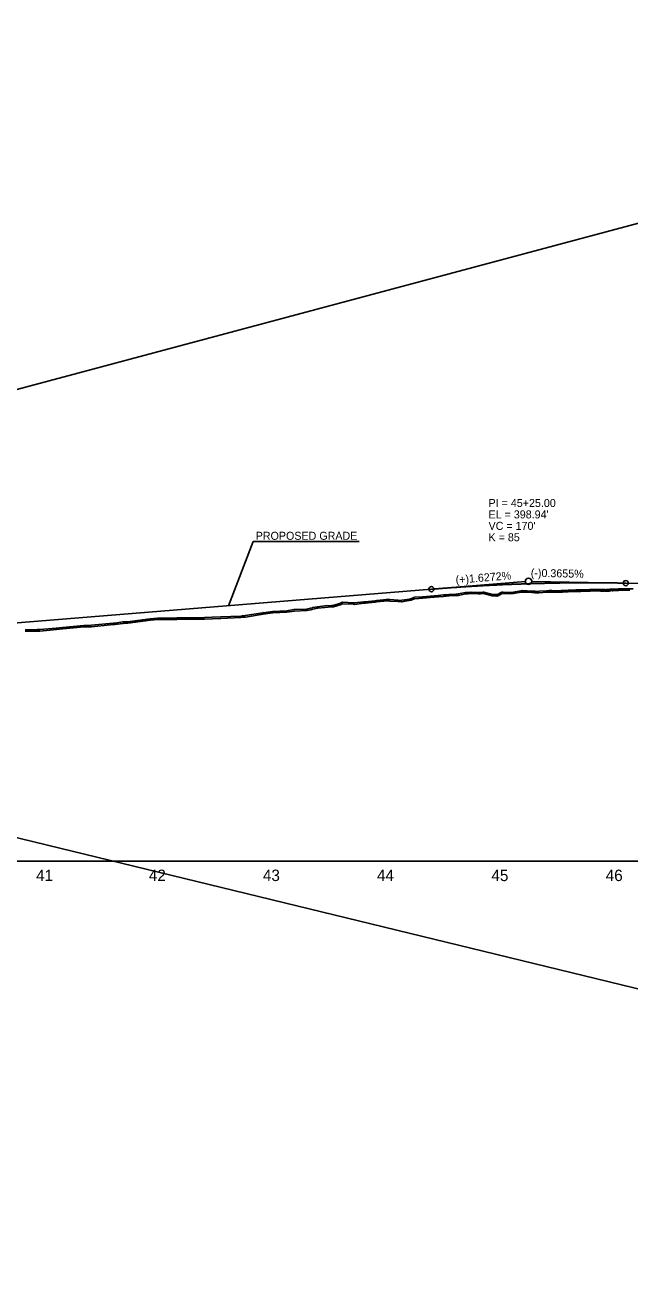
# Model space of a CAD drawing. Extents: x 1625686 to 1640492, y 1161393 to 1175642.
# Drawn here: x 1638996 to 1639525, y 1174544 to 1175642 of the extents above; entities that cross this region are included whole.
import ezdxf

# ---------------------------------------------------------------- set-up
doc = ezdxf.new("R2010")
doc.units = 0
for name, color, linetype in [('Exist Profile Cell', 7, 'Continuous'), ('Exist Vertical Profile Horizontal Axis Label Major', 7, 'Continuous'), ('Prop Vertical Profile Curve Label', 7, 'Continuous'), ('Prop Vertical Profile Grade', 7, 'Continuous'), ('Prop Vertical Profile Grade Label', 7, 'Continuous'), ('Prop VPI Label', 7, 'Continuous'), ('Scratch_Level_1', 7, 'Continuous'), ('Scratch_Level_3', 7, 'Continuous')]:
    doc.layers.add(name, color=color, linetype=linetype)

msp = doc.modelspace()

# ---------------------------------------------------------------- linework, layer by layer
at = {"layer": 'Exist Profile Cell'}
msp.add_line((1635911.8, 1174910.8), (1640378.1, 1174910.8), dxfattribs=at)
at = {"layer": 'Prop Vertical Profile Curve Label'}
for centre in [(1639351.8, 1175148.6), (1639521.8, 1175153.9)]:
    msp.add_circle(centre, 2.25, dxfattribs=at)
at = {"layer": 'Prop Vertical Profile Grade'}
for p, q in [((1639521.8, 1175153.9), (1639936.8, 1175146.4)), ((1638766.8, 1175101), (1639351.8, 1175148.6))]:
    msp.add_line(p, q, dxfattribs=at)
msp.add_spline([(1639351.8, 1175148.6), (1639355.2, 1175148.8), (1639358.6, 1175149.1), (1639362, 1175149.4), (1639365.4, 1175149.6), (1639368.8, 1175149.9), (1639372.2, 1175150.1), (1639375.6, 1175150.3), (1639379, 1175150.6), (1639382.4, 1175150.8), (1639385.8, 1175151), (1639389.2, 1175151.2), (1639392.6, 1175151.4), (1639396, 1175151.6), (1639399.4, 1175151.8), (1639402.8, 1175152), (1639406.2, 1175152.1), (1639409.6, 1175152.3), (1639413, 1175152.5), (1639416.4, 1175152.6), (1639419.8, 1175152.7), (1639423.2, 1175152.9), (1639426.6, 1175153), (1639430, 1175153.1), (1639433.4, 1175153.3), (1639436.8, 1175153.4), (1639440.2, 1175153.5), (1639443.6, 1175153.6), (1639447, 1175153.7), (1639450.4, 1175153.7), (1639453.8, 1175153.8), (1639457.2, 1175153.9), (1639460.6, 1175154), (1639464, 1175154), (1639467.4, 1175154.1), (1639470.8, 1175154.1), (1639474.2, 1175154.1), (1639477.6, 1175154.2), (1639481, 1175154.2), (1639484.4, 1175154.2), (1639487.8, 1175154.2), (1639491.2, 1175154.2), (1639494.6, 1175154.2), (1639498, 1175154.2), (1639501.4, 1175154.2), (1639504.8, 1175154.2), (1639508.2, 1175154.1), (1639511.6, 1175154.1), (1639515, 1175154), (1639518.4, 1175154), (1639521.8, 1175153.9)], degree=3, dxfattribs=at)
at = {"layer": 'Prop VPI Label'}
for p, q in [((1639196, 1175190.4), (1639174.3, 1175134.1)), ((1639288.6, 1175190.4), (1639196, 1175190.4)), ((1639351.8, 1175148.6), (1639434, 1175155.3)), ((1639521.8, 1175153.9), (1639439.5, 1175155.4))]:
    msp.add_line(p, q, dxfattribs=at)
msp.add_circle((1639436.8, 1175155.5), 2.75, dxfattribs=at)
at = {"layer": 'Scratch_Level_1'}
for p, q in [((1639303.9, 1175138.6), (1639309.9, 1175139.4)), ((1639310, 1175139.4), (1639312.2, 1175139.6)), ((1639310.1, 1175138.1), (1639312.3, 1175138.3)), ((1639312.3, 1175139.6), (1639312.6, 1175139.6)), ((1639312.4, 1175138.3), (1639312.7, 1175138.4)), ((1639381.8, 1175145.7), (1639384, 1175145.8)), ((1639381.9, 1175144.4), (1639384, 1175144.6)), ((1639384, 1175145.8), (1639386.2, 1175146)), ((1639384.1, 1175144.6), (1639386.3, 1175144.7)), ((1639411, 1175144.9), (1639413.3, 1175145.9)), ((1639411.6, 1175143.7), (1639413.8, 1175144.8)), ((1639431.9, 1175147.3), (1639435.6, 1175147.1)), ((1639431.9, 1175146.1), (1639435.5, 1175145.9)), ((1639435.5, 1175145.9), (1639439.8, 1175145.7)), ((1639435.6, 1175147.1), (1639439.9, 1175146.9)), ((1639439.8, 1175145.7), (1639442.4, 1175145.5)), ((1639439.9, 1175146.9), (1639442.4, 1175146.8)), ((1639457, 1175146.1), (1639461.2, 1175145.9)), ((1639457.1, 1175147.4), (1639461.3, 1175147.2)), ((1639465.3, 1175147.3), (1639466.5, 1175147.4)), ((1639465.4, 1175146.1), (1639466.6, 1175146.1)), ((1639466.6, 1175147.4), (1639469.6, 1175147.5)), ((1639466.6, 1175146.1), (1639469.7, 1175146.3)), ((1639473.4, 1175147.7), (1639473.9, 1175147.7)), ((1639473.5, 1175146.5), (1639474, 1175146.5)), ((1639473.9, 1175147.7), (1639478.3, 1175147.9)), ((1639474, 1175146.5), (1639478.3, 1175146.7)), ((1639482.5, 1175148), (1639485, 1175148.1)), ((1639482.6, 1175146.7), (1639485, 1175146.8)), ((1639485, 1175148.1), (1639486.8, 1175148.1)), ((1639485, 1175146.8), (1639486.9, 1175146.9)), ((1639491.5, 1175148.3), (1639495.5, 1175148.3)), ((1639491.5, 1175147.1), (1639495.5, 1175147.1)), ((1639495.5, 1175148.3), (1639496.9, 1175148.3)), ((1639495.5, 1175147.1), (1639496.9, 1175147.1)), ((1639496.9, 1175148.3), (1639499.8, 1175148.3)), ((1639496.9, 1175147.1), (1639499.8, 1175147)), ((1639504.9, 1175148.2), (1639506.1, 1175148.3)), ((1639505, 1175147), (1639506.2, 1175147)), ((1639508.7, 1175148.5), (1639509.9, 1175148.5)), ((1639510.3, 1175148.5), (1639512.8, 1175148.7)), ((1639510.4, 1175147.3), (1639512.8, 1175147.4)), ((1639512.8, 1175148.7), (1639514.2, 1175148.7)), ((1639512.9, 1175147.4), (1639514.2, 1175147.5)), ((1639516.8, 1175148.8), (1639517.2, 1175148.8)), ((1639516.9, 1175147.6), (1639517.3, 1175147.6)), ((1639517.2, 1175148.8), (1639518.1, 1175148.8)), ((1639517.3, 1175147.6), (1639518.1, 1175147.6)), ((1639524, 1175148.9), (1639525.5, 1175148.9)), ((1639524, 1175147.6), (1639525.5, 1175147.6)), ((1639204.5, 1175128), (1639212.8, 1175129)), ((1639204.7, 1175126.8), (1639212.9, 1175127.8)), ((1639247.9, 1175132.5), (1639252.1, 1175133.2)), ((1639248.1, 1175131.2), (1639252.3, 1175131.9)), ((1639252.2, 1175133.2), (1639258.6, 1175133.9)), ((1639252.4, 1175131.9), (1639258.7, 1175132.6)), ((1639258.7, 1175133.9), (1639264.3, 1175134.3)), ((1639258.7, 1175132.6), (1639264.4, 1175133.1)), ((1639274.3, 1175137.1), (1639283.4, 1175136.8)), ((1639274.3, 1175135.8), (1639283.4, 1175135.6)), ((1639304.1, 1175137.4), (1639310, 1175138.1)), ((1639105.9, 1175122.8), (1639109.1, 1175123.1)), ((1639106.1, 1175121.6), (1639109.2, 1175121.9)), ((1639109.3, 1175123.1), (1639112.2, 1175123.2)), ((1639109.3, 1175121.9), (1639112.2, 1175122))]:
    msp.add_line(p, q, dxfattribs=at)
for points in [[(1639293, 1175137.5), (1639294.1, 1175137.5), (1639302.3, 1175138.3), (1639303.8, 1175138.6)], [(1639312.9, 1175139.6), (1639315.4, 1175139.5), (1639322.7, 1175139.1)], [(1639312.9, 1175138.4), (1639315.3, 1175138.2), (1639322.6, 1175137.9)], [(1639322.8, 1175139.1), (1639325.7, 1175138.8), (1639326, 1175138.9), (1639328.4, 1175139.4)], [(1639328.6, 1175139.4), (1639332.3, 1175140), (1639333.9, 1175140.2), (1639336.3, 1175141.3)], [(1639328.8, 1175138.2), (1639332.5, 1175138.7), (1639334.2, 1175139), (1639336.8, 1175140.1)], [(1639337.1, 1175141.5), (1639344.1, 1175142), (1639350.6, 1175142.5), (1639354.1, 1175142.8), (1639357.8, 1175143.2), (1639362.3, 1175143.6)], [(1639337.2, 1175140.2), (1639344.2, 1175140.7), (1639350.7, 1175141.2), (1639354.2, 1175141.6), (1639358, 1175141.9), (1639362.5, 1175142.3)], [(1639362.4, 1175143.6), (1639364.7, 1175143.8), (1639367.1, 1175143.9)], [(1639362.5, 1175142.3), (1639364.8, 1175142.5), (1639367.2, 1175142.7)], [(1639367.1, 1175143.9), (1639373.2, 1175144.3), (1639375.3, 1175144.4), (1639381.5, 1175145.6)], [(1639367.2, 1175142.7), (1639373.3, 1175143), (1639375.5, 1175143.1), (1639381.7, 1175144.4)], [(1639386.4, 1175144.7), (1639392.7, 1175144.4), (1639394.8, 1175144.6), (1639397, 1175144.7)], [(1639386.5, 1175146), (1639392.7, 1175145.7), (1639394.7, 1175145.8), (1639396.9, 1175146)], [(1639397.4, 1175144.7), (1639405, 1175142.8), (1639409.1, 1175142.6), (1639410, 1175142.7), (1639410.8, 1175143.1), (1639411.2, 1175143.5)], [(1639397.7, 1175145.9), (1639405.2, 1175144), (1639409.1, 1175143.9), (1639409.7, 1175143.9), (1639410.1, 1175144.1), (1639410.4, 1175144.4)], [(1639414.4, 1175144.9), (1639420.3, 1175144.5), (1639423.5, 1175144.7), (1639430.3, 1175145.9)], [(1639414.5, 1175146.1), (1639420.3, 1175145.8), (1639423.3, 1175145.9), (1639430.1, 1175147.2)], [(1639430.5, 1175147.2), (1639431, 1175147.2), (1639431.6, 1175147.3)], [(1639430.5, 1175146), (1639431.1, 1175146), (1639431.7, 1175146)], [(1639442.4, 1175145.5), (1639444.1, 1175145.4), (1639446.2, 1175145.5), (1639452.8, 1175146)], [(1639442.5, 1175146.8), (1639444.1, 1175146.7), (1639446.1, 1175146.8), (1639452.7, 1175147.2)], [(1639452.7, 1175147.2), (1639454.7, 1175147.3), (1639456.8, 1175147.4)], [(1639452.8, 1175146), (1639454.7, 1175146), (1639456.9, 1175146.1)], [(1639461.2, 1175145.9), (1639462.2, 1175145.9), (1639465.4, 1175146.1)], [(1639461.3, 1175147.2), (1639462.2, 1175147.2), (1639465.3, 1175147.3)], [(1639469.6, 1175147.5), (1639471.4, 1175147.6), (1639473.4, 1175147.7)], [(1639469.7, 1175146.3), (1639471.4, 1175146.4), (1639473.5, 1175146.5)], [(1639478.4, 1175147.9), (1639480.2, 1175147.9), (1639482.5, 1175148)], [(1639478.4, 1175146.7), (1639480.2, 1175146.6), (1639482.6, 1175146.7)], [(1639486.8, 1175148.1), (1639490.2, 1175148.2), (1639491.2, 1175148.3)], [(1639486.9, 1175146.9), (1639490.3, 1175147), (1639491.3, 1175147.1)], [(1639499.8, 1175148.3), (1639502.2, 1175148.3), (1639502.9, 1175148.3)], [(1639499.8, 1175147), (1639502.2, 1175147), (1639502.9, 1175147)], [(1639503.4, 1175146.9), (1639503.6, 1175146.9), (1639504.1, 1175146.9), (1639504.9, 1175147)], [(1639503.8, 1175148.1), (1639504, 1175148.1), (1639504.8, 1175148.2)], [(1639506.2, 1175147), (1639507.3, 1175147), (1639508.2, 1175147.3)], [(1639506.3, 1175148.3), (1639507.1, 1175148.3), (1639507.8, 1175148.5)], [(1639508.6, 1175147.3), (1639510, 1175147.2), (1639510.1, 1175147.2)], [(1639514.3, 1175148.7), (1639515.4, 1175148.8), (1639516.8, 1175148.8)], [(1639514.3, 1175147.5), (1639515.4, 1175147.5), (1639516.9, 1175147.6)], [(1639518.1, 1175148.8), (1639519.2, 1175148.8), (1639521.1, 1175148.9)], [(1639518.1, 1175147.6), (1639519.2, 1175147.6), (1639521.2, 1175147.6)], [(1639521.2, 1175148.9), (1639523.4, 1175148.9), (1639524, 1175148.9)], [(1639521.2, 1175147.6), (1639523.4, 1175147.6), (1639524, 1175147.6)], [(1639525.5, 1175148.9), (1639525.9, 1175148.9), (1639527, 1175148.9), (1639528.4, 1175148.9)], [(1639186.8, 1175125.4), (1639188.9, 1175125.5), (1639204.4, 1175128)], [(1639212.9, 1175129), (1639225.2, 1175129.8), (1639231.6, 1175130.7)], [(1639213, 1175127.8), (1639225.3, 1175128.5), (1639231.8, 1175129.4)], [(1639231.8, 1175130.7), (1639242.6, 1175131.2), (1639246, 1175131.9), (1639247.6, 1175132.4)], [(1639231.9, 1175129.4), (1639242.7, 1175130), (1639246.3, 1175130.6), (1639248, 1175131.2)], [(1639264.3, 1175134.3), (1639265.9, 1175134.4), (1639272.3, 1175136.5), (1639273.2, 1175136.9)], [(1639264.4, 1175133.1), (1639266.1, 1175133.2), (1639272.8, 1175135.3), (1639273.7, 1175135.7)], [(1639283.7, 1175135.5), (1639284.4, 1175135.3), (1639292.8, 1175136.3)], [(1639284.1, 1175136.7), (1639284.5, 1175136.6), (1639292.7, 1175137.5)], [(1639293, 1175136.3), (1639294.2, 1175136.3), (1639302.4, 1175137.1), (1639304, 1175137.4)], [(1639322.7, 1175137.9), (1639325.7, 1175137.6), (1639326.2, 1175137.6), (1639328.7, 1175138.2)], [(1639029.2, 1175115), (1639047.8, 1175116.9), (1639048.5, 1175116.9)], [(1639048.7, 1175116.9), (1639054.3, 1175117), (1639073.5, 1175119)], [(1639048.7, 1175115.7), (1639054.3, 1175115.8), (1639073.6, 1175117.7)], [(1639073.7, 1175119), (1639074.8, 1175119), (1639081.9, 1175119.9)], [(1639073.7, 1175117.7), (1639074.9, 1175117.7), (1639082, 1175118.6)], [(1639082.1, 1175119.9), (1639086, 1175120.1), (1639105.8, 1175122.8)], [(1639082.1, 1175118.6), (1639086.1, 1175118.8), (1639106, 1175121.5)], [(1639112.2, 1175123.2), (1639126.1, 1175123.2), (1639129.1, 1175123.4)], [(1639112.2, 1175122), (1639126.1, 1175122), (1639129.1, 1175122.1)], [(1639129.2, 1175123.4), (1639150.9, 1175123.6), (1639153.3, 1175123.8)], [(1639129.2, 1175122.1), (1639150.9, 1175122.4), (1639153.3, 1175122.5)], [(1639153.3, 1175123.8), (1639160.1, 1175124.1), (1639167.5, 1175124.4)], [(1639153.3, 1175122.5), (1639160.2, 1175122.8), (1639167.5, 1175123.1)], [(1639167.5, 1175124.4), (1639185, 1175125.1), (1639186.4, 1175125.4)], [(1639167.5, 1175123.1), (1639185.1, 1175123.9), (1639186.6, 1175124.1)], [(1639186.8, 1175124.1), (1639189.1, 1175124.2), (1639204.6, 1175126.8)], [(1638996.3, 1175113.1), (1639007, 1175113.2), (1639009.1, 1175113.3), (1639023.6, 1175114.5), (1639029.2, 1175115)], [(1638996.3, 1175111.9), (1639007, 1175111.9), (1639009.2, 1175112), (1639023.8, 1175113.2), (1639029.4, 1175113.8)], [(1639029.4, 1175113.8), (1639047.9, 1175115.6), (1639048.6, 1175115.7)]]:
    msp.add_lwpolyline(points, dxfattribs=at)
for centre, radius, start, end in [((1639304.3, 1175136.1), 2.5, 97.3926, 100.858), ((1639310.2, 1175136.9), 2.5, 94.6193, 97.3926), ((1639312.4, 1175137.1), 2.5, 93.9476, 94.6193), ((1639312.4, 1175137.1), 1.25, 93.9476, 94.6193), ((1639312.8, 1175137.1), 2.5, 87.1466, 93.9476), ((1639312.8, 1175137.1), 1.25, 87.1466, 93.9476), ((1639322.6, 1175136.7), 2.5, 84.1047, 87.3612), ((1639328.9, 1175136.9), 2.5, 98.3239, 102.1934), ((1639337.3, 1175139), 2.5, 94.2508, 112.9541), ((1639337.3, 1175139), 1.25, 94.2508, 112.9541), ((1639362.6, 1175141.1), 2.5, 94.2169, 95.4818), ((1639362.6, 1175141.1), 1.25, 94.2169, 95.4818), ((1639367.3, 1175141.4), 2.5, 92.9168, 94.3822), ((1639367.3, 1175141.4), 1.25, 92.9168, 94.3822), ((1639382, 1175143.2), 2.5, 94.1965, 101.4805), ((1639382, 1175143.2), 1.25, 94.1965, 101.4805), ((1639384.1, 1175143.3), 2.5, 93.7655, 94.1965), ((1639384.1, 1175143.3), 1.25, 93.7655, 94.1965), ((1639386.4, 1175143.5), 2.5, 87.3911, 93.7655), ((1639386.4, 1175143.5), 1.25, 87.3911, 93.7655), ((1639397.1, 1175143.5), 2.5, 76.0153, 93.9476), ((1639397.1, 1175143.5), 1.25, 76.0153, 93.9476), ((1639412.1, 1175142.6), 2.5, 114.7526, 133.7236), ((1639412.1, 1175142.6), 1.25, 114.7526, 133.7236), ((1639414.4, 1175143.6), 2.5, 86.6248, 114.7526), ((1639414.4, 1175143.6), 1.25, 86.6248, 114.7526), ((1639430.6, 1175144.7), 2.5, 92.7649, 100.4912), ((1639430.6, 1175144.7), 1.25, 92.7649, 100.4912), ((1639431.8, 1175144.8), 2.5, 87.2388, 94.9283), ((1639431.8, 1175144.8), 1.25, 87.2388, 94.9283), ((1639435.4, 1175144.6), 1.25, 87.2354, 87.2388), ((1639435.4, 1175144.6), 2.5, 87.2354, 87.2388), ((1639439.7, 1175144.4), 1.25, 87.2321, 87.2354), ((1639439.7, 1175144.4), 2.5, 87.2321, 87.2354), ((1639442.3, 1175144.3), 2.5, 86.689, 87.2321), ((1639442.3, 1175144.3), 1.25, 86.689, 87.2321), ((1639452.8, 1175144.7), 2.5, 92.2481, 93.8382), ((1639452.8, 1175144.7), 1.25, 92.2481, 93.8382), ((1639457, 1175144.9), 2.5, 87.421, 92.5346), ((1639457, 1175144.9), 1.25, 87.421, 92.5346), ((1639461.2, 1175144.7), 1.25, 87.4111, 87.421), ((1639461.2, 1175144.7), 2.5, 87.4111, 87.421), ((1639465.5, 1175144.8), 2.5, 93.1155, 93.128), ((1639465.5, 1175144.8), 1.25, 93.1155, 93.128), ((1639466.7, 1175144.9), 2.5, 92.4381, 93.1155), ((1639466.7, 1175144.9), 1.25, 92.4381, 93.1155), ((1639469.7, 1175145), 2.5, 92.4254, 92.4381), ((1639469.7, 1175145), 1.25, 92.4254, 92.4381), ((1639473.5, 1175145.2), 2.5, 92.5421, 93.023), ((1639473.5, 1175145.2), 1.25, 92.5421, 93.023), ((1639474, 1175145.2), 2.5, 92.53, 92.5421), ((1639474, 1175145.2), 1.25, 92.53, 92.5421), ((1639478.4, 1175145.4), 2.5, 89.1847, 92.53), ((1639478.4, 1175145.4), 1.25, 89.1847, 92.53), ((1639482.6, 1175145.5), 2.5, 91.9474, 91.9636), ((1639482.6, 1175145.5), 1.25, 91.9474, 91.9636), ((1639485.1, 1175145.6), 2.5, 91.5664, 91.9474), ((1639485.1, 1175145.6), 1.25, 91.5664, 91.9474), ((1639486.9, 1175145.6), 2.5, 91.5501, 91.5664), ((1639486.9, 1175145.6), 1.25, 91.5501, 91.5664), ((1639491.5, 1175145.8), 2.5, 89.9405, 96.2914), ((1639491.5, 1175145.8), 1.25, 89.9405, 96.2914), ((1639495.5, 1175145.8), 2.5, 89.9331, 89.9405), ((1639495.5, 1175145.8), 1.25, 89.9331, 89.9405), ((1639496.9, 1175145.8), 2.5, 89.4016, 89.9331), ((1639496.9, 1175145.8), 1.25, 89.4016, 89.9331), ((1639499.8, 1175145.8), 2.5, 89.394, 89.4016), ((1639499.8, 1175145.8), 1.25, 89.394, 89.4016), ((1639503, 1175145.8), 2.5, 69.4483, 91.8684), ((1639503, 1175145.8), 1.25, 66.9741, 91.8684), ((1639505, 1175145.7), 2.5, 91.9853, 95.7529), ((1639505, 1175145.7), 1.25, 91.9853, 95.7529), ((1639506.2, 1175145.8), 2.5, 89.3174, 91.9853), ((1639506.2, 1175145.8), 1.25, 89.3174, 91.9853), ((1639508.5, 1175146), 2.5, 85.9806, 105.5959), ((1639508.5, 1175146), 1.25, 85.9806, 105.5959), ((1639510.5, 1175146), 2.5, 93.1907, 104.5413), ((1639510.5, 1175146), 1.25, 93.1907, 107.416), ((1639512.9, 1175146.2), 2.5, 92.7647, 93.1907), ((1639512.9, 1175146.2), 1.25, 92.7647, 93.1907), ((1639514.3, 1175146.2), 2.5, 91.1256, 92.7647), ((1639514.3, 1175146.2), 1.25, 91.1256, 92.7647), ((1639516.9, 1175146.3), 2.5, 91.4585, 91.4846), ((1639516.9, 1175146.3), 1.25, 91.4585, 91.4846), ((1639517.3, 1175146.3), 2.5, 91.3484, 91.4585), ((1639517.3, 1175146.3), 1.25, 91.3484, 91.4585), ((1639518.1, 1175146.3), 2.5, 90.9329, 91.3484), ((1639518.1, 1175146.3), 1.25, 90.9329, 91.3484), ((1639521.2, 1175146.4), 2.5, 89.9004, 91.3294), ((1639521.2, 1175146.4), 1.25, 89.9004, 91.3294), ((1639524, 1175146.4), 2.5, 90.1898, 90.464), ((1639524, 1175146.4), 1.25, 90.1898, 90.464), ((1639525.5, 1175146.4), 2.5, 90.1614, 90.1898), ((1639204.8, 1175125.6), 2.5, 96.7976, 99.3617), ((1639213, 1175126.5), 2.5, 93.4365, 96.7976), ((1639213, 1175126.5), 1.25, 93.4365, 96.7976), ((1639232, 1175128.2), 2.5, 92.8256, 97.7721), ((1639232, 1175128.2), 1.25, 92.8256, 97.7721), ((1639248.3, 1175130), 2.5, 99.421, 107.9697), ((1639248.3, 1175130), 1.25, 99.421, 107.9697), ((1639252.5, 1175130.7), 2.5, 96.3811, 99.421), ((1639252.5, 1175130.7), 1.25, 96.3811, 99.421), ((1639258.8, 1175131.4), 2.5, 94.1736, 96.3811), ((1639258.8, 1175131.4), 1.25, 94.1736, 96.3811), ((1639264.5, 1175131.8), 2.5, 93.5481, 94.1736), ((1639264.5, 1175131.8), 1.25, 93.5481, 94.1736), ((1639274.2, 1175134.6), 2.5, 88.3729, 113.7703), ((1639274.2, 1175134.6), 1.25, 88.3729, 113.7703), ((1639283.3, 1175134.3), 2.5, 71.3999, 88.3729), ((1639283.3, 1175134.3), 1.25, 71.3999, 88.3729), ((1639293, 1175135), 2.5, 89.8778, 96.536), ((1639293, 1175135), 1.25, 89.8778, 96.536), ((1639304.3, 1175136.1), 1.25, 97.3926, 100.858), ((1639310.2, 1175136.9), 1.25, 94.6193, 97.3926), ((1639322.6, 1175136.7), 1.25, 84.1047, 87.3612), ((1639328.9, 1175136.9), 1.25, 98.3239, 102.1934), ((1639048.7, 1175114.4), 2.5, 90.944, 95.8571), ((1639073.8, 1175116.5), 2.5, 90.8298, 95.7145), ((1639073.8, 1175116.5), 1.25, 90.8298, 95.7145), ((1639082.2, 1175117.4), 2.5, 92.7936, 96.9762), ((1639082.2, 1175117.4), 1.25, 92.7936, 96.9762), ((1639106.2, 1175120.3), 2.5, 96.1185, 97.8277), ((1639106.2, 1175120.3), 1.25, 96.1185, 97.8277), ((1639109.3, 1175120.6), 2.5, 91.0814, 96.1185), ((1639109.3, 1175120.6), 1.25, 91.0814, 96.1185), ((1639112.2, 1175120.7), 2.5, 90.1366, 91.0814), ((1639112.2, 1175120.7), 1.25, 90.1366, 91.0814), ((1639129.2, 1175120.9), 2.5, 90.6378, 92.9195), ((1639129.2, 1175120.9), 1.25, 90.6378, 92.9195), ((1639153.4, 1175121.3), 2.5, 92.4366, 93.0502), ((1639153.4, 1175121.3), 1.25, 92.4366, 93.0502), ((1639167.6, 1175121.9), 2.5, 92.432, 92.4462), ((1639167.6, 1175121.9), 1.25, 92.432, 92.4462), ((1639186.9, 1175122.9), 2.5, 92.3737, 99.7421), ((1639186.9, 1175122.9), 1.25, 92.3737, 99.7421), ((1639204.8, 1175125.6), 1.25, 96.7976, 99.3617), ((1639029.5, 1175112.5), 2.5, 95.642, 95.8083), ((1639029.5, 1175112.5), 1.25, 95.642, 95.8083), ((1639048.7, 1175114.4), 1.25, 90.944, 95.8571)]:
    msp.add_arc(centre, radius, start, end, dxfattribs=at)
at = {"layer": 'Scratch_Level_3'}
for p, q in [((1636069.4, 1175642), (1640127.7, 1174654.2)), ((1636080.3, 1174544.5), (1640138.7, 1175631))]:
    msp.add_line(p, q, dxfattribs=at)
msp.add_lwpolyline([(1635911.8, 1174910.8), (1640049.2, 1174910.8), (1640049.2, 1175362.5)], dxfattribs=at)

# ---------------------------------------------------------------- texts
at = {"layer": 'Exist Vertical Profile Horizontal Axis Label Major'}
for s, p in [('41', (1639006, 1174893.3)), ('42', (1639104.6, 1174893.3)), ('43', (1639204.4, 1174893.3)), ('44', (1639304.2, 1174893.3)), ('45', (1639404.3, 1174893.3)), ('46', (1639504.3, 1174893.3))]:
    msp.add_text(s, height=10, dxfattribs=at).set_placement(p)
at = {"layer": 'Prop Vertical Profile Curve Label'}
for s, p in [("VC = 170'", (1639401.8, 1175200.5)), ('K = 85', (1639401.8, 1175190.5))]:
    msp.add_text(s, height=7, dxfattribs=at).set_placement(p)
at = {"layer": 'Prop Vertical Profile Grade Label'}
for s, rotation, p in [('(+)1.6272%', 4.6514, (1639373.3, 1175153.3)), ('(-)0.3655%', 358.9532, (1639438.7, 1175159.4))]:
    msp.add_text(s, height=7, rotation=rotation, dxfattribs=at).set_placement(p)
at = {"layer": 'Prop VPI Label'}
for s, p in [('PI = 45+25.00', (1639401.8, 1175220.5)), ("EL = 398.94'", (1639401.8, 1175210.5)), ('PROPOSED GRADE', (1639198.1, 1175191.8))]:
    msp.add_text(s, height=7, dxfattribs=at).set_placement(p)

doc.saveas('drawing.dxf')
